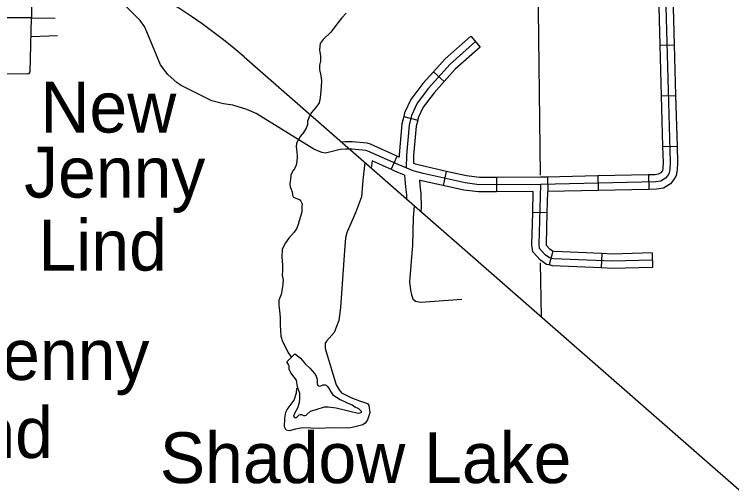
# Model space of a CAD drawing. Extents: x 1370567 to 1373900, y 377514 to 379648.
# Drawn here: x 1372612.6 to 1372825.7, y 378368 to 378508 of the extents above; entities that cross this region are included whole.
import ezdxf

# ---------------------------------------------------------------- set-up
doc = ezdxf.new("R2010")
doc.units = 0
doc.layers.add('Default', color=7, linetype='Continuous')

msp = doc.modelspace()

# ---------------------------------------------------------------- linework, layer by layer
at = {"layer": 'Default'}
for p, q in [((1372748.2, 378501.5), (1372751.04, 378498.29)), ((1372804.37, 378498.86), (1372808.66, 378498.98)), ((1372737.14, 378490.92), (1372740.33, 378488.06)), ((1372804.79, 378483.78), (1372809.07, 378483.9)), ((1372728.3, 378477.63), (1372732.46, 378476.6)), ((1372805.2, 378468.7), (1372809.49, 378468.82)), ((1372724.58, 378461.95), (1372726.34, 378465.86)), ((1372740.92, 378461.36), (1372739.98, 378457.18)), ((1372801.04, 378460.31), (1372801.13, 378456.02)), ((1372755.83, 378459.56), (1372755.85, 378455.28)), ((1372770.99, 378459.68), (1372771.08, 378455.39)), ((1372785.96, 378459.99), (1372786.05, 378455.71)), ((1372770.92, 378449.04), (1372766.63, 378449.15)), ((1372772.55, 378437.71), (1372771.46, 378433.56)), ((1372787.14, 378436.95), (1372786.96, 378432.67)), ((1372802.07, 378437.15), (1372802.19, 378432.86))]:
    msp.add_line(p, q, dxfattribs=at)
for points in [[(1372617.83, 378517.68), (1372617.72, 378506.92)], [(1372768.96, 378460.21), (1372768.24, 378517.56)], [(1372806.1, 378514), (1372807.48, 378463.97), (1372807.39, 378462.03), (1372807.16, 378460.83), (1372806.79, 378460.15), (1372806.1, 378459.32), (1372804.68, 378458.44), (1372803.16, 378458.21), (1372768.99, 378457.49), (1372750.66, 378457.39), (1372746.55, 378457.91), (1372734.11, 378460.69), (1372731.08, 378461.52), (1372725.94, 378463.69), (1372717.67, 378467.4), (1372717.07, 378467.58), (1372712.84, 378467.98), (1372710.99, 378467.98), (1372709.39, 378467.81), (1372706.27, 378467.04), (1372704.93, 378466.81), (1372704.02, 378466.99), (1372701.59, 378467.93), (1372684.44, 378478.56), (1372681.67, 378479.76), (1372677.56, 378481.02), (1372674.73, 378481.45), (1372671.28, 378482.31), (1372662.2, 378486.85), (1372660.98, 378487.66), (1372658.26, 378490.11), (1372656.07, 378493), (1372652.04, 378502.85), (1372651.3, 378504.36), (1372650.05, 378506.19), (1372641.3, 378515.08)], [(1372712.16, 378467.98), (1372710.99, 378467.98), (1372709.39, 378467.81), (1372706.27, 378467.04), (1372704.93, 378466.81), (1372704.02, 378466.99), (1372701.59, 378467.93), (1372684.44, 378478.56), (1372681.67, 378479.76), (1372677.56, 378481.02), (1372674.73, 378481.45), (1372671.28, 378482.31), (1372662.2, 378486.85), (1372660.98, 378487.66), (1372658.26, 378490.11), (1372656.07, 378493), (1372652.04, 378502.85), (1372651.3, 378504.36), (1372650.05, 378506.19), (1372641.3, 378515.08)], [(1372803.93, 378514.17), (1372804.37, 378498.86)], [(1372808.23, 378513.93), (1372808.66, 378498.98)], [(1372608.73, 378490.43), (1372616.56, 378490.28), (1372617.04, 378490.4), (1372617.38, 378490.97), (1372617.72, 378506.92), (1372601.89, 378506.92), (1372588.87, 378507.4)], [(1372711.23, 378508.33), (1372709.88, 378506.98), (1372708.43, 378505.07), (1372706.67, 378502.68), (1372704.39, 378500.56), (1372703.51, 378499.31), (1372703.3, 378497.5), (1372703.61, 378495.53), (1372703.61, 378494.08), (1372703.25, 378492.88), (1372703.3, 378491.64), (1372703.72, 378489.72), (1372703.92, 378488.37), (1372703.77, 378486.46), (1372703.51, 378483.24), (1372703.2, 378481.74), (1372702.21, 378480.34), (1372700.76, 378478.78), (1372700.09, 378477.23), (1372699.73, 378476.29), (1372699.73, 378475.15), (1372699.36, 378474.22), (1372698.53, 378472.92), (1372697.65, 378471.84), (1372696.41, 378469.71), (1372696.31, 378468.67), (1372696.57, 378467.17), (1372696.67, 378465.82), (1372696.57, 378464.32), (1372696.36, 378463.23), (1372695.84, 378462.09), (1372695.37, 378461.52), (1372694.8, 378460.27), (1372694.7, 378458.93), (1372694.49, 378457.79), (1372694.54, 378456.8), (1372694.86, 378456.08), (1372695.17, 378455.3), (1372695.22, 378454.31), (1372695.58, 378453.74), (1372696.25, 378453.43), (1372697.03, 378453.07), (1372697.45, 378452.86), (1372697.71, 378452.55), (1372698.12, 378451.72), (1372698.07, 378450.84), (1372698.02, 378449.39), (1372697.65, 378447.99), (1372697.24, 378446.64), (1372696.93, 378445.6), (1372696.57, 378444.51), (1372695.74, 378443.27), (1372694.18, 378441.51), (1372693.15, 378440.11), (1372692.16, 378438.29), (1372692.11, 378435.91), (1372692.32, 378433.58), (1372692.27, 378431.97), (1372692.21, 378430.52), (1372692.47, 378429.07), (1372692.32, 378427.1), (1372691.9, 378424.76), (1372691.23, 378423.16), (1372691.18, 378421.5), (1372691.44, 378420.05), (1372691.64, 378417.82), (1372691.64, 378415.59), (1372691.7, 378414.19), (1372691.75, 378412.42), (1372692.27, 378410.82), (1372693.3, 378408.95), (1372693.87, 378407.71), (1372694.94, 378406.13)], [(1372617.72, 378506.92), (1372624.72, 378506.85)], [(1372617.6, 378501.44), (1372625.45, 378501.72)], [(1372748.2, 378501.5), (1372740.57, 378494.74), (1372737.14, 378490.92)], [(1372749.62, 378499.9), (1372742.08, 378493.22), (1372735.66, 378486.06), (1372732.26, 378481.58), (1372730.6, 378477.99), (1372729.89, 378475.1), (1372729.11, 378466.17), (1372728.99, 378462.4)], [(1372804.37, 378498.86), (1372804.79, 378483.78)], [(1372808.66, 378498.98), (1372809.07, 378483.9)], [(1372751.04, 378498.29), (1372743.59, 378491.7), (1372740.33, 378488.06)], [(1372680.86, 378495.34), (1372842.86, 378353.74)], [(1372737.14, 378490.92), (1372734, 378487.43), (1372730.41, 378482.69), (1372728.57, 378478.7), (1372728.3, 378477.63)], [(1372740.33, 378488.06), (1372737.31, 378484.7), (1372734.11, 378480.47), (1372732.63, 378477.27), (1372732.46, 378476.6)], [(1372804.79, 378483.78), (1372805.2, 378468.7)], [(1372809.07, 378483.9), (1372809.49, 378468.82)], [(1372728.3, 378477.63), (1372727.77, 378475.46), (1372726.97, 378466.3), (1372726.95, 378465.59)], [(1372732.46, 378476.6), (1372732.01, 378474.75), (1372731.25, 378466.04), (1372731.18, 378463.8)], [(1372712.31, 378470.12), (1372710.87, 378470.12), (1372709.84, 378470.01)], [(1372726.95, 378465.59), (1372718.4, 378469.42), (1372717.47, 378469.69), (1372712.94, 378470.12), (1372712.31, 378470.12)], [(1372805.2, 378468.7), (1372805.33, 378463.99), (1372805.26, 378462.28), (1372805.12, 378461.56), (1372805.01, 378461.35), (1372804.68, 378460.96), (1372803.92, 378460.49), (1372802.98, 378460.35), (1372801.04, 378460.31)], [(1372809.49, 378468.82), (1372809.62, 378463.96), (1372809.52, 378461.78), (1372809.2, 378460.1), (1372808.57, 378458.94), (1372807.53, 378457.68), (1372805.43, 378456.38), (1372803.35, 378456.07), (1372801.13, 378456.02)], [(1372725.68, 378461.47), (1372725.09, 378461.72), (1372718.9, 378464.5), (1372718.67, 378462.29)], [(1372716.7, 378464.02), (1372716.15, 378458.73), (1372715.72, 378453.79), (1372713.98, 378449.05), (1372711.49, 378443.37), (1372711.12, 378442.15), (1372710.86, 378440.63), (1372709.54, 378420.94), (1372709, 378417.11), (1372707.63, 378413.55), (1372706.17, 378411.83), (1372705.32, 378410.92), (1372704.97, 378410.38), (1372704.92, 378408.78), (1372708.25, 378397.96), (1372709.08, 378396.48), (1372709.82, 378395.62), (1372712.56, 378394.19), (1372715.16, 378393.25), (1372717.5, 378392.47), (1372717.93, 378391.84), (1372718.19, 378389.68), (1372717.53, 378387.62), (1372716.81, 378386.54), (1372716.16, 378386.08), (1372713.02, 378385.34), (1372711.76, 378385.11), (1372706.82, 378385.23), (1372703.17, 378385.03), (1372698.23, 378385.21), (1372696.2, 378384.81), (1372694.32, 378384.27), (1372693.35, 378384.5), (1372692.92, 378385.53), (1372692.98, 378388.04), (1372693.26, 378389.81), (1372693.66, 378390.66), (1372695.78, 378393.43), (1372696.46, 378395.63), (1372696.52, 378396.97)], [(1372741.39, 378461.25), (1372734.62, 378462.77), (1372731.79, 378463.54), (1372731.18, 378463.8)], [(1372728.53, 378460.27), (1372725.68, 378461.47)], [(1372728.53, 378460.27), (1372728.59, 378459.04), (1372728.86, 378456.78), (1372729.15, 378454.37), (1372729.17, 378453.12)], [(1372755.83, 378459.56), (1372750.79, 378459.53), (1372746.92, 378460.02), (1372741.39, 378461.25)], [(1372801.04, 378460.31), (1372785.96, 378459.99)], [(1372740.46, 378457.07), (1372733.59, 378458.6), (1372732.94, 378458.78)], [(1372732.94, 378458.78), (1372733.12, 378457.3), (1372733.43, 378454.66), (1372733.48, 378450.78), (1372733.37, 378449.44)], [(1372770.88, 378459.67), (1372768.96, 378459.63), (1372755.83, 378459.56)], [(1372785.96, 378459.99), (1372770.88, 378459.67)], [(1372755.85, 378455.28), (1372750.54, 378455.25), (1372746.19, 378455.79), (1372740.46, 378457.07)], [(1372802.13, 378435), (1372790.23, 378434.67), (1372772.81, 378435.42), (1372771.64, 378435.73), (1372770.33, 378436.62), (1372768.68, 378438.44), (1372768.53, 378439.65), (1372768.99, 378457.49)], [(1372801.13, 378456.02), (1372786.05, 378455.71)], [(1372766.79, 378455.34), (1372755.85, 378455.28)], [(1372766.63, 378449.15), (1372766.79, 378455.34)], [(1372770.92, 378449.04), (1372771.08, 378455.39)], [(1372786.05, 378455.71), (1372771.08, 378455.39)], [(1372731.36, 378451.2), (1372731.08, 378447.59), (1372730.9, 378439.49), (1372730.03, 378428.55), (1372730.29, 378426.11), (1372730.6, 378424.68), (1372730.99, 378423.55), (1372731.77, 378422.8), (1372733.43, 378422.54), (1372745.53, 378423.37)], [(1372771.46, 378433.56), (1372770.74, 378433.75), (1372768.91, 378435), (1372766.63, 378437.51), (1372766.38, 378439.55), (1372766.63, 378449.15)], [(1372772.55, 378437.71), (1372772.54, 378437.71), (1372771.74, 378438.25), (1372770.72, 378439.38), (1372770.68, 378439.75), (1372770.92, 378449.04)], [(1372787.14, 378436.95), (1372773.13, 378437.55), (1372772.55, 378437.71)], [(1372802.07, 378437.15), (1372790.24, 378436.81), (1372787.14, 378436.95)], [(1372769.2, 378418.13), (1372768.94, 378434.15)], [(1372786.96, 378432.67), (1372772.49, 378433.29), (1372771.46, 378433.56)], [(1372802.19, 378432.86), (1372790.21, 378432.52), (1372786.96, 378432.67)], [(1372696, 378407.14), (1372693.56, 378404.8)], [(1372696, 378407.14), (1372697.59, 378405.87), (1372699.11, 378404.15), (1372700.45, 378402.87), (1372701.77, 378401.35), (1372702.29, 378400.59), (1372702.49, 378399.93), (1372702.56, 378399.24), (1372702.56, 378398.72), (1372702.56, 378398.24), (1372702.77, 378397.79), (1372703.15, 378397.61), (1372703.67, 378397.68), (1372704.36, 378397.93), (1372704.98, 378397.93), (1372705.29, 378397.82), (1372705.67, 378397.51), (1372706.12, 378396.82), (1372706.6, 378395.85), (1372707.29, 378394.99), (1372708.36, 378394.26), (1372709.4, 378393.64), (1372710.71, 378392.98), (1372711.65, 378392.5), (1372712.99, 378391.98), (1372713.82, 378391.46), (1372714.86, 378390.94), (1372715.41, 378390.49), (1372715.69, 378390.18), (1372715.62, 378389.63), (1372715.31, 378389.56), (1372714.75, 378389.42), (1372712.3, 378390.08), (1372708.26, 378391.01), (1372705.84, 378391.36), (1372704.67, 378391.36), (1372703.74, 378391.01), (1372703.08, 378390.81), (1372701.91, 378390.49), (1372701.11, 378390.29), (1372700.49, 378390.05), (1372699.66, 378389.22), (1372699.25, 378388.87), (1372698.93, 378388.77), (1372698.59, 378388.8), (1372698, 378389.01), (1372697.73, 378389.08), (1372697.55, 378389.04), (1372697.14, 378388.91), (1372696.69, 378388.46), (1372696.31, 378388.21), (1372695.96, 378388.18), (1372695.83, 378388.25), (1372695.69, 378388.8), (1372695.96, 378389.6), (1372696.86, 378391.15), (1372697.38, 378392.71), (1372697.45, 378393.81), (1372697.48, 378395.44), (1372696.79, 378397.41), (1372696.45, 378399.38), (1372694.76, 378401.49), (1372694.31, 378402.63), (1372694.24, 378403.59), (1372694.03, 378403.97), (1372693.56, 378404.8)]]:
    msp.add_lwpolyline(points, dxfattribs=at)
msp.add_arc((1372579.09, 378378.92), 154.64, 48.844, 228.844, dxfattribs=at)

# ---------------------------------------------------------------- texts
for s, height, p in [('New', 15.086, (1372620.38, 378472.89)), ('Jenny', 15.086, (1372615.55, 378453.57)), ('Lind', 15.086, (1372619.81, 378431.89)), ('Old Jenny', 15.086, (1372561.93, 378399.41)), ('Lind', 15.086, (1372585.94, 378376.24)), ('Shadow Lake', 15.0857, (1372655.85, 378368.78))]:
    msp.add_text(s, height=height, dxfattribs=at).set_placement(p)

doc.saveas('drawing.dxf')
